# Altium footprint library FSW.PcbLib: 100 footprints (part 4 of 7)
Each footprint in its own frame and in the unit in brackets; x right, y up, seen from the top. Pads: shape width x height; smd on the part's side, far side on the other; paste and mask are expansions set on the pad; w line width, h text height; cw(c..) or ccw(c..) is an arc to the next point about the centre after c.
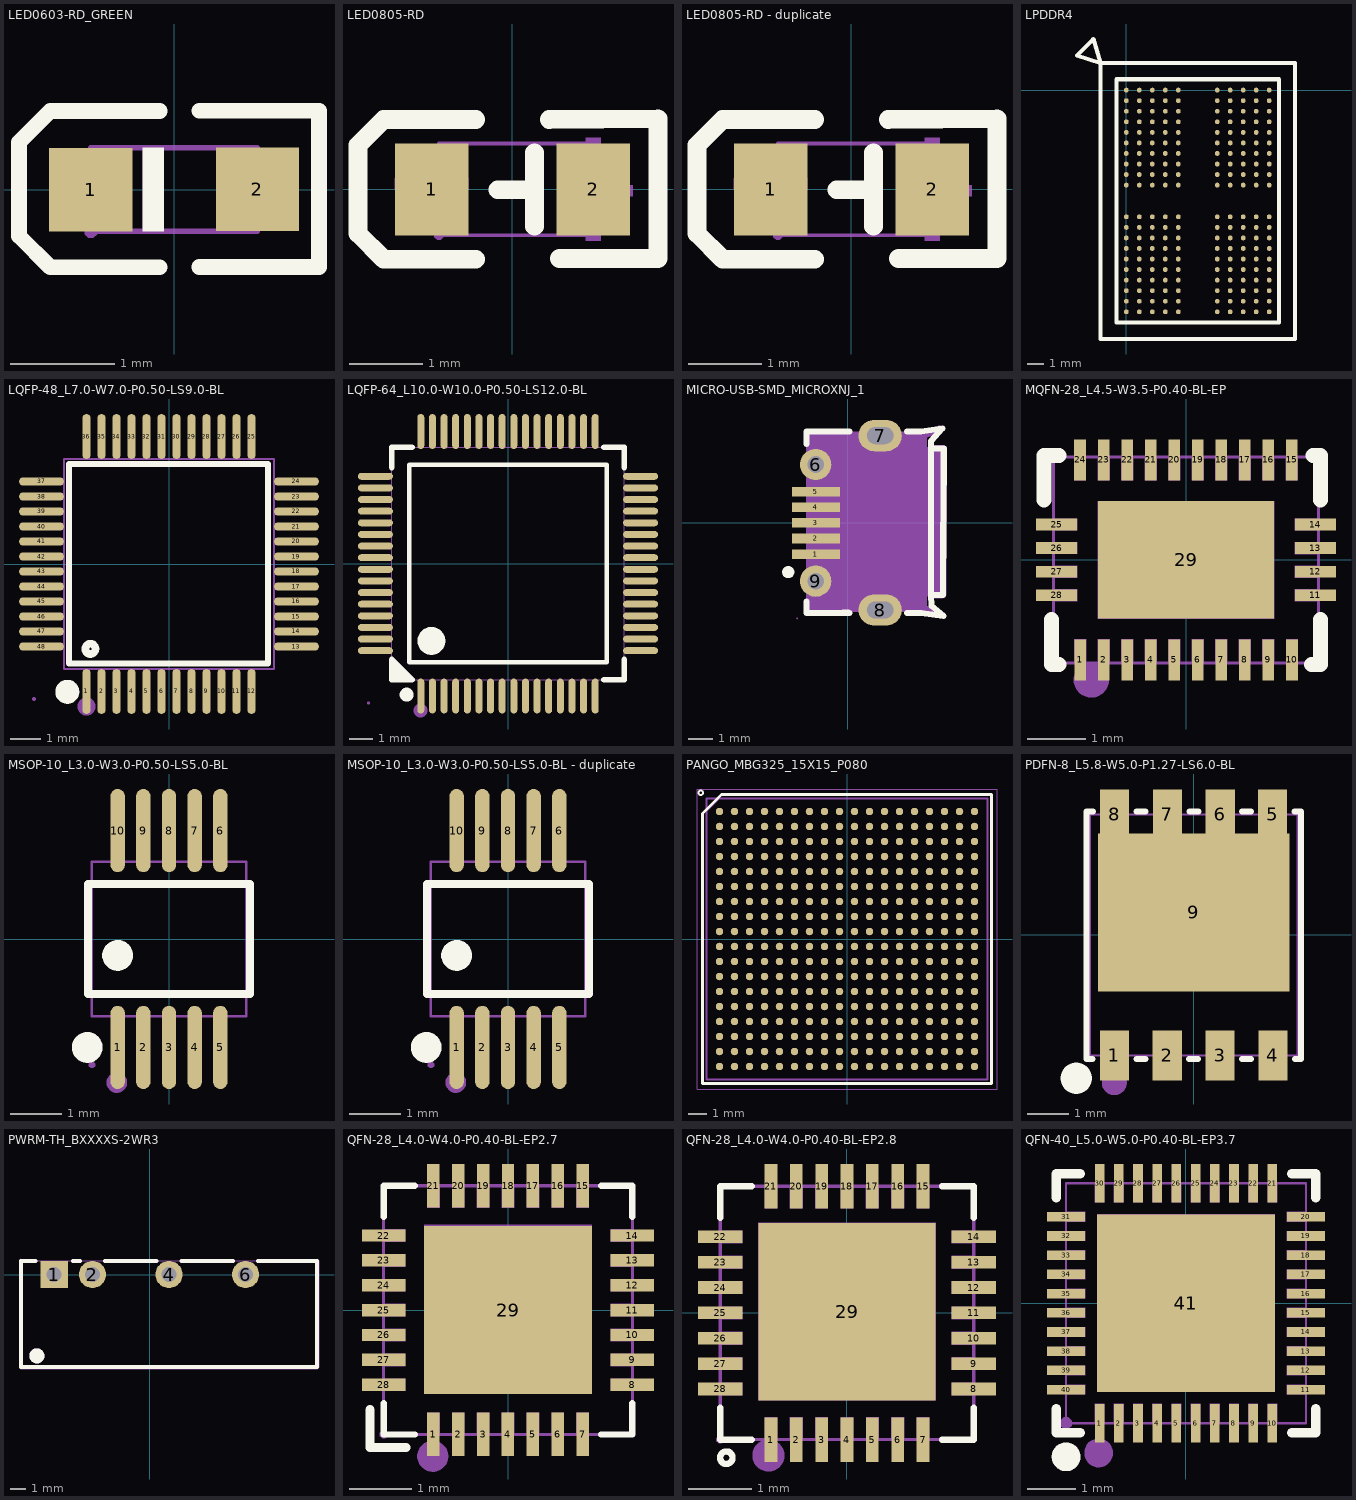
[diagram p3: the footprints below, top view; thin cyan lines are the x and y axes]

## LED0603-RD_GREEN [mm]
pads (2):
  rect 0.8x0.8 smd: 1(-0.799,-0.003) 2(0.799,0.003)
Top Overlay:
  region: -0.3,0.4 -0.3,-0.4 -0.1,-0.4 -0.1,0.4
  lines w0.15: -0.14,-0.746 -1.19,-0.746 -1.49,-0.446 -1.49,-0.346 -1.49,0.354 -1.49,0.454 -1.19,0.754 -0.14,0.754 ; 0.24,-0.744 1.39,-0.744 ; 0.24,0.757 1.39,0.757 1.39,-0.723
Mechanical 2:
  region: 0.529,0.068 1.069,0.068 1.069,-0.062 0.529,-0.062
  region: 0.735,-0.267 0.735,0.273 0.865,0.273 0.865,-0.267
  region: -1.07,0.062 -0.53,0.062 -0.53,-0.068 -1.07,-0.068
  region: -0.3,0.4 -0.3,-0.4 -0.1,-0.4 -0.1,0.4
Mechanical 6:
  lines w0.051: -0.8,-0.4 -0.8,0.4 0.8,0.4 0.8,-0.4 -0.8,-0.4
Mechanical 8:
  region: -0.74,-0.403 -0.74,-0.428 -0.775,-0.463 -0.824,-0.463 -0.86,-0.428 -0.86,-0.403 -0.86,-0.379 -0.824,-0.343 -0.775,-0.343 -0.74,-0.379 -0.74,-0.403
Mechanical 9:
  region: 0.5,-0.396 0.5,0.404 0.8,0.404 0.8,-0.396
  region: -0.8,-0.403 -0.8,0.397 -0.5,0.397 -0.5,-0.403
3D body "LED0603-RD-YELLOW.step": height 0.55, standoff -0.01, extent -0.81,-0.41 0.81,0.41

## LED0805-RD [mm]
pads (2):
  rect 1x1.25 smd: 1(-1.1,0) 2(1.1,0)
Top Overlay:
  lines w0.254: -0.5,-0.95 -1.75,-0.95 ; -0.5,0.95 -1.75,0.95 ; -0.2,-0.005 0.3,-0.005 ; 0.3,-0.5 0.3,0.5 ; 0.5,0.95 1.98,0.96 1.98,-0.94 0.64,-0.94 ; -1.75,-0.95 -2.1,-0.6 -2.1,0.6 -1.75,0.95 ; -1.75,-0.95 -1.75,-0.95 ; -1.75,0.95 -1.75,0.95
Mechanical 2:
  region: -1.6,0 -0.6,0 -0.6,0.15 -1.6,0.15
  region: 0.635,-0.094 1.635,-0.094 1.635,0.056 0.635,0.056
  region: 1,0.7 1.2,0.7 1.2,-0.7 1,-0.7
Mechanical 6:
  lines w0.051: -1,-0.625 1,-0.625 1,0.625 -1,0.625 -1,-0.625
Mechanical 8:
  region: -0.939,-0.625 -0.939,-0.65 -0.975,-0.686 -1.025,-0.686 -1.061,-0.65 -1.061,-0.625 -1.061,-0.6 -1.025,-0.564 -0.975,-0.564 -0.939,-0.6 -0.939,-0.625 -0.94,-0.625
Mechanical 9:
  region: -0.65,-0.625 -1,-0.625 -1,0.625 -0.65,0.625
  region: 1,-0.625 0.65,-0.625 0.65,0.625 1,0.625
3D body "LED0805-RD.step": height 1, standoff -0.01, extent -1.137,-0.625 0.883,0.635

## LED0805-RD - duplicate [mm]
pads (2):
  rect 1x1.25 smd: 1(-1.1,0) 2(1.1,0)
Top Overlay:
  lines w0.254: -0.5,-0.95 -1.75,-0.95 ; -0.5,0.95 -1.75,0.95 ; -0.2,-0.005 0.3,-0.005 ; 0.3,-0.5 0.3,0.5 ; 0.5,0.95 1.98,0.96 1.98,-0.94 0.64,-0.94 ; -1.75,-0.95 -2.1,-0.6 -2.1,0.6 -1.75,0.95 ; -1.75,-0.95 -1.75,-0.95 ; -1.75,0.95 -1.75,0.95
Mechanical 2:
  region: -1.6,0 -0.6,0 -0.6,0.15 -1.6,0.15
  region: 0.635,-0.094 1.635,-0.094 1.635,0.056 0.635,0.056
  region: 1,0.7 1.2,0.7 1.2,-0.7 1,-0.7
Mechanical 6:
  lines w0.051: -1,-0.625 1,-0.625 1,0.625 -1,0.625 -1,-0.625
Mechanical 8:
  region: -0.939,-0.625 -0.939,-0.65 -0.975,-0.686 -1.025,-0.686 -1.061,-0.65 -1.061,-0.625 -1.061,-0.6 -1.025,-0.564 -0.975,-0.564 -0.939,-0.6 -0.939,-0.625 -0.94,-0.625
Mechanical 9:
  region: -0.65,-0.625 -1,-0.625 -1,0.625 -0.65,0.625
  region: 1,-0.625 0.65,-0.625 0.65,0.625 1,0.625

## LPDDR4 [mm]
pads (200):
  round 0.3 smd paste+0.051: A1(0,0) A2(0.8,0) A3(1.6,0) A4(2.4,0) A5(3.2,0) A8(5.6,0) A9(6.4,0) A10(7.2,0) A11(8,0) A12(8.8,0) AA1(0,-13) AA2(0.8,-13) AA3(1.6,-13) AA4(2.4,-13) AA5(3.2,-13) AA8(5.6,-13) AA9(6.4,-13) AA10(7.2,-13) AA11(8,-13) AA12(8.8,-13) AB1(0,-13.65) AB2(0.8,-13.65) AB3(1.6,-13.65) AB4(2.4,-13.65) AB5(3.2,-13.65) AB8(5.6,-13.65) AB9(6.4,-13.65) AB10(7.2,-13.65) AB11(8,-13.65) AB12(8.8,-13.65) B1(0,-0.65) B2(0.8,-0.65) B3(1.6,-0.65) B4(2.4,-0.65) B5(3.2,-0.65) B8(5.6,-0.65) B9(6.4,-0.65) B10(7.2,-0.65) B11(8,-0.65) B12(8.8,-0.65) C1(0,-1.3) C2(0.8,-1.3) C3(1.6,-1.3) C4(2.4,-1.3) C5(3.2,-1.3) C8(5.6,-1.3) C9(6.4,-1.3) C10(7.2,-1.3) C11(8,-1.3) C12(8.8,-1.3) D1(0,-1.95) D2(0.8,-1.95) D3(1.6,-1.95) D4(2.4,-1.95) D5(3.2,-1.95) D8(5.6,-1.95) D9(6.4,-1.95) D10(7.2,-1.95) D11(8,-1.95) D12(8.8,-1.95) E1(0,-2.6) E2(0.8,-2.6) E3(1.6,-2.6) E4(2.4,-2.6) E5(3.2,-2.6) E8(5.6,-2.6) E9(6.4,-2.6) E10(7.2,-2.6) E11(8,-2.6) E12(8.8,-2.6) F1(0,-3.25) F2(0.8,-3.25) F3(1.6,-3.25) F4(2.4,-3.25) F5(3.2,-3.25) F8(5.6,-3.25) F9(6.4,-3.25) F10(7.2,-3.25) F11(8,-3.25) F12(8.8,-3.25) G1(0,-3.9) G2(0.8,-3.9) G3(1.6,-3.9) G4(2.4,-3.9) G5(3.2,-3.9) G8(5.6,-3.9) G9(6.4,-3.9) G10(7.2,-3.9) G11(8,-3.9) G12(8.8,-3.9) H1(0,-4.55) H2(0.8,-4.55) H3(1.6,-4.55) H4(2.4,-4.55) H5(3.2,-4.55) H8(5.6,-4.55) H9(6.4,-4.55) H10(7.2,-4.55) H11(8,-4.55) H12(8.8,-4.55) J1(0,-5.2) J2(0.8,-5.2) J3(1.6,-5.2) J4(2.4,-5.2) J5(3.2,-5.2) J8(5.6,-5.2) J9(6.4,-5.2) J10(7.2,-5.2) J11(8,-5.2) J12(8.8,-5.2) K1(0,-5.85) K2(0.8,-5.85) K3(1.6,-5.85) K4(2.4,-5.85) K5(3.2,-5.85) K8(5.6,-5.85) K9(6.4,-5.85) K10(7.2,-5.85) K11(8,-5.85) K12(8.8,-5.85) N1(0,-7.8) N2(0.8,-7.8) N3(1.6,-7.8) N4(2.4,-7.8) N5(3.2,-7.8) N8(5.6,-7.8) N9(6.4,-7.8) N10(7.2,-7.8) N11(8,-7.8) N12(8.8,-7.8) P1(0,-8.45) P2(0.8,-8.45) P3(1.6,-8.45) P4(2.4,-8.45) P5(3.2,-8.45) P8(5.6,-8.45) P9(6.4,-8.45) P10(7.2,-8.45) P11(8,-8.45) P12(8.8,-8.45) R1(0,-9.1) R2(0.8,-9.1) R3(1.6,-9.1) R4(2.4,-9.1) R5(3.2,-9.1) R8(5.6,-9.1) R9(6.4,-9.1) R10(7.2,-9.1) R11(8,-9.1) R12(8.8,-9.1) T1(0,-9.75) T2(0.8,-9.75) T3(1.6,-9.75) T4(2.4,-9.75) T5(3.2,-9.75) T8(5.6,-9.75) T9(6.4,-9.75) T10(7.2,-9.75) T11(8,-9.75) T12(8.8,-9.75) U1(0,-10.4) U2(0.8,-10.4) U3(1.6,-10.4) U4(2.4,-10.4) U5(3.2,-10.4) U8(5.6,-10.4) U9(6.4,-10.4) U10(7.2,-10.4) U11(8,-10.4) U12(8.8,-10.4) V1(0,-11.05) V2(0.8,-11.05) V3(1.6,-11.05) V4(2.4,-11.05) V5(3.2,-11.05) V8(5.6,-11.05) V9(6.4,-11.05) V10(7.2,-11.05) V11(8,-11.05) V12(8.8,-11.05) W1(0,-11.7) W2(0.8,-11.7) W3(1.6,-11.7) W4(2.4,-11.7) W5(3.2,-11.7) W8(5.6,-11.7) W9(6.4,-11.7) W10(7.2,-11.7) W11(8,-11.7) W12(8.8,-11.7) Y1(0,-12.35) Y2(0.8,-12.35) Y3(1.6,-12.35) Y4(2.4,-12.35) Y5(3.2,-12.35) Y8(5.6,-12.35) Y9(6.4,-12.35) Y10(7.2,-12.35) Y11(8,-12.35) Y12(8.8,-12.35)
Top Overlay:
  lines w0.254: -1.6,1.675 -1.6,-15.325 10.4,-15.325 10.4,1.675 -1.6,1.675 ; -1.6,1.675 -3.048,2.134 -2.032,3.15 -1.6,1.675 ; -0.6,-14.32 -0.6,0.67 9.4,0.67 9.4,-14.32 -0.6,-14.32
3D body "BGA-200_L15.0-W10.0_K4F8E304HB-MGCJ.step": height 0.9, standoff -0.01, extent -0.555,-14.358 9.445,0.642

## LQFP-48_L7.0-W7.0-P0.50-LS9.0-BL [mm]
pads (48):
  oval 0.27x1.5 smd paste+0 mask+0.05: 1(-2.75,-4.25) 2(-2.25,-4.25) 3(-1.75,-4.25) 4(-1.25,-4.25) 5(-0.75,-4.25) 6(-0.25,-4.25) 7(0.25,-4.25) 8(0.75,-4.25) 9(1.25,-4.25) 10(1.75,-4.25) 11(2.25,-4.25) 12(2.75,-4.25) 25(2.75,4.25) 26(2.25,4.25) 27(1.75,4.25) 28(1.25,4.25) 29(0.75,4.25) 30(0.25,4.25) 31(-0.25,4.25) 32(-0.75,4.25) 33(-1.25,4.25) 34(-1.75,4.25) 35(-2.25,4.25) 36(-2.75,4.25)
  oval 1.5x0.27 smd paste+0 mask+0.05: 13(4.25,-2.75) 14(4.25,-2.25) 15(4.25,-1.75) 16(4.25,-1.25) 17(4.25,-0.75) 18(4.25,-0.25) 19(4.25,0.25) 20(4.25,0.75) 21(4.25,1.25) 22(4.25,1.75) 23(4.25,2.25) 24(4.25,2.75) 37(-4.25,2.75) 38(-4.25,2.25) 39(-4.25,1.75) 40(-4.25,1.25) 41(-4.25,0.75) 42(-4.25,0.25) 43(-4.25,-0.25) 44(-4.25,-0.75) 45(-4.25,-1.25) 46(-4.25,-1.75) 47(-4.25,-2.25) 48(-4.25,-2.75)
Top Overlay:
  circle w0.254: c-2.62,-2.83 r0.17
  lines w0.2: -2.896,3.34 3.302,3.34 3.302,-3.315 -3.327,-3.315 -3.327,3.34 -2.565,3.34
  lines w0.4: -3.39,-4.06 ccw(c-3.389,-4.26) -3.387,-4.06
Mechanical 2:
  circle w0.3: c-2.75,-4.75 r0.15
Mechanical 6:
  lines w0.051: -3.5,-3.5 3.5,-3.5 3.5,3.5 -3.5,3.5 -3.5,-3.5
Mechanical 7:
  drawing of 48 lines, arcs and shapes, not listed
Mechanical 8:
  region: -4.44,-4.5 -4.44,-4.525 -4.475,-4.56 -4.525,-4.56 -4.56,-4.525 -4.56,-4.5 -4.56,-4.475 -4.525,-4.44 -4.475,-4.44 -4.44,-4.475 -4.44,-4.5
Mechanical 9:
  drawing of 48 lines, arcs and shapes, not listed

## LQFP-64_L10.0-W10.0-P0.50-LS12.0-BL [mm]
pads (64):
  oval 0.3x1.5 smd: 1(-3.75,-5.688) 2(-3.25,-5.688) 3(-2.75,-5.688) 4(-2.25,-5.688) 5(-1.75,-5.688) 6(-1.25,-5.688) 7(-0.75,-5.688) 8(-0.25,-5.688) 9(0.25,-5.688) 10(0.75,-5.688) 11(1.25,-5.688) 12(1.75,-5.688) 13(2.25,-5.688) 14(2.75,-5.688) 15(3.25,-5.688) 16(3.75,-5.688) 33(3.75,5.688) 34(3.25,5.688) 35(2.75,5.688) 36(2.25,5.688) 37(1.75,5.688) 38(1.25,5.688) 39(0.75,5.688) 40(0.25,5.688) 41(-0.25,5.688) 42(-0.75,5.688) 43(-1.25,5.688) 44(-1.75,5.688) 45(-2.25,5.688) 46(-2.75,5.688) 47(-3.25,5.688) 48(-3.75,5.688)
  oval 1.5x0.3 smd: 17(5.7,-3.738) 18(5.7,-3.238) 19(5.7,-2.738) 20(5.7,-2.238) 21(5.7,-1.738) 22(5.7,-1.238) 23(5.7,-0.738) 24(5.7,-0.238) 25(5.7,0.262) 26(5.7,0.762) 27(5.7,1.262) 28(5.7,1.762) 29(5.7,2.262) 30(5.7,2.762) 31(5.7,3.262) 32(5.7,3.762) 49(-5.7,3.762) 50(-5.7,3.262) 51(-5.7,2.762) 52(-5.7,2.262) 53(-5.7,1.762) 54(-5.7,1.262) 55(-5.7,0.762) 56(-5.7,0.262) 57(-5.7,-0.238) 58(-5.7,-0.738) 59(-5.7,-1.238) 60(-5.7,-1.738) 61(-5.7,-2.238) 62(-5.7,-2.738) 63(-5.7,-3.238) 64(-5.7,-3.738)
Top Overlay:
  region: -4.131,-4.988 -5,-4.119 -5,-4.988
  lines w0.2: -4.25,-4.238 -4.25,4.262 4.25,4.262 4.25,-4.238 -4.25,-4.238
  lines w0.254: -5,4.143 -5,5.012 -4.131,5.012 ; 4.131,-4.988 5,-4.988 5,-4.119 ; 4.131,5.012 5,5.012 5,4.143 ; -5,-4.119 -5,-4.119 ; -5,-4.119 -4.131,-4.988 -5,-4.988 -5,-4.119
  lines w0.3: -4.361,-5.478 ccw(c-4.36,-5.628) -4.359,-5.478
  lines w0.6: -3.299,-3.013 ccw(c-3.297,-3.313) -3.294,-3.013
Mechanical 2:
  circle w0.3: c-3.76,-6.308 r0.15
Mechanical 6:
  lines w0.051: -5,-4.988 5,-4.988 5,5.012 -5,5.012 -5,-4.988
Mechanical 7:
  drawing of 64 lines, arcs and shapes, not listed
Mechanical 8:
  region: -5.94,-5.988 -5.94,-6.013 -5.975,-6.048 -6.025,-6.048 -6.06,-6.013 -6.06,-5.988 -6.06,-5.963 -6.025,-5.928 -5.975,-5.928 -5.94,-5.963 -5.94,-5.988
Mechanical 9:
  drawing of 64 lines, arcs and shapes, not listed

## MICRO-USB-SMD_MICROXNJ_1 [mm]
pads (9):
  rect 2x0.4 smd paste-100 mask+0.051: 1(-1.332,-1.3) 2(-1.332,-0.65) 3(-1.332,0) 4(-1.332,0.65) 5(-1.332,1.3)
  round 1.3 hole 0.7 paste-2539.97 mask+0.051: 6(-1.34,2.425) 9(-1.34,-2.425)
  oval 1.8x1.3 hole 0.7 slot 1.1 at 0 deg paste-2539.97 mask+0.051: 7(1.34,3.625) 8(1.34,-3.625)
Mid-Layer 2:
  lines w0.1: -4.186,-7.897 ccw(c-4.136,-7.897) -4.086,-7.897 ccw(c-4.136,-7.897) -4.186,-7.897
Top Overlay:
  lines w0.254: -1.725,-3.274 -1.725,-3.745 0.058,-3.745 ; -1.725,3.274 -1.725,3.79 0.066,3.79 ; -0.196,-3.731 0.012,-3.735 ; -0.163,-3.732 0.012,-3.733 ; 2.448,3.79 3.041,3.79 ; 2.456,-3.745 3.052,-3.745 3.967,-3.87 3.471,-3.45 3.451,-3 ; 3.041,3.8 3.926,3.93 3.451,3.4 3.451,3.1 ; 3.451,-3 3.451,3.1 ; 3.451,-3 3.951,-3 3.981,3.09 3.451,3.1 ; -2.61,-2.049 ccw(c-2.483,-2.049) -2.356,-2.049 ccw(c-2.483,-2.049) -2.61,-2.049
Top Paste:
  region: -1.957,-1.125 -1.957,-1.475 -0.707,-1.475 -0.707,-1.125
  region: -1.957,-0.475 -1.957,-0.825 -0.707,-0.825 -0.707,-0.475
  region: -1.957,1.475 -1.957,1.125 -0.707,1.125 -0.707,1.475
  region: -1.957,0.825 -1.957,0.475 -0.707,0.475 -0.707,0.825
  region: -1.957,0.175 -1.957,-0.175 -0.707,-0.175 -0.707,0.175
Mechanical 5:
  region: 3.451,-2.873 3.825,-2.873 3.854,2.965 3.449,2.973 3.401,2.984 3.361,3.012 3.334,3.054 3.325,3.102 3.336,3.151 3.364,3.191 3.405,3.218 3.454,3.227 3.984,3.217 4.032,3.207 4.072,3.179 4.099,3.138 4.108,3.089 4.078,-3.001 4.069,-3.049 4.041,-3.09 4,-3.117 3.951,-3.127 3.451,-3.127 3.403,-3.117 3.362,-3.09 3.334,-3.049 3.324,-3 3.334,-2.951 3.362,-2.91 3.403,-2.883
Mechanical 9:
  region: -1.725,-3.7 -1.725,3.79 3.255,3.79 3.805,4.05 3.865,4.03 3.865,3.83 3.275,3.54 3.275,3.15 3.875,3.15 3.865,-3.03 3.865,-3.05 3.275,-3.05 3.275,-3.45 3.875,-3.74 3.865,-3.97 3.265,-3.7 -1.715,-3.7
Mechanical 11:
  region: -2.08,-3.97 -2.089,-3.949 -2.11,-3.94 -2.131,-3.949 -2.14,-3.97 -2.131,-3.991 -2.11,-4 -2.089,-3.991
Mechanical 12:
  region: -1.11,1.175 -2.11,1.175 -2.11,1.425 -1.11,1.425
  region: -1.11,0.525 -2.11,0.525 -2.11,0.775 -1.11,0.775
  region: -1.11,-0.125 -2.11,-0.125 -2.11,0.125 -1.11,0.125
  region: -1.11,-0.775 -2.11,-0.775 -2.11,-0.525 -1.11,-0.525
  region: -1.11,-1.425 -2.11,-1.425 -2.11,-1.175 -1.11,-1.175
  region: 0.875,-3.775 0.875,-3.475 1.785,-3.475 1.785,-3.775
  region: 0.875,3.475 0.875,3.775 1.785,3.775 1.785,3.475
  region: -1.24,-2.675 -1.44,-2.675 -1.44,-2.175 -1.24,-2.175
  region: -1.24,2.175 -1.44,2.175 -1.44,2.675 -1.24,2.675
3D body "MICRO-USB-SMD_MICROXNJ_1.step": height 2.71, standoff -0.95, extent -1.9,-4 4.064,4

## MQFN-28_L4.5-W3.5-P0.40-BL-EP [mm]
pads (29):
  rect 0.2x0.7 smd paste-100 mask+0.051: 1(-1.8,-1.7) 2(-1.4,-1.7) 3(-1,-1.7) 4(-0.6,-1.7) 5(-0.2,-1.7) 6(0.2,-1.7) 7(0.6,-1.7) 8(1,-1.7) 9(1.4,-1.7) 10(1.8,-1.7) 15(1.8,1.7) 16(1.4,1.7) 17(1,1.7) 18(0.6,1.7) 19(0.2,1.7) 20(-0.2,1.7) 21(-0.6,1.7) 22(-1,1.7) 23(-1.4,1.7) 24(-1.8,1.7)
  rect 0.7x0.2 smd paste-100 mask+0.051: 11(2.2,-0.6) 12(2.2,-0.2) 13(2.2,0.2) 14(2.2,0.6) 25(-2.2,0.6) 26(-2.2,0.2) 27(-2.2,-0.2) 28(-2.2,-0.6)
  rect 3x2 smd paste-100 mask+0.051: 29(0,0)
Top Overlay:
  lines w0.254: -2.413,1.016 -2.413,1.778 -2.159,1.778 ; -2.286,-1.016 -2.286,-1.778 -2.159,-1.778 ; 2.131,-1.778 2.286,-1.778 2.286,-1.016 ; 2.159,1.778 2.286,1.778 2.286,1.016
Top Paste:
  region: -1.2,0.8 1.2,0.8 1.2,-0.8 -1.2,-0.8
  region: -0.1,-2.05 -0.1,-1.35 -0.3,-1.35 -0.3,-2.05
  region: 0.1,-1.35 0.1,-2.05 0.3,-2.05 0.3,-1.35
  region: -0.5,-2.05 -0.5,-1.35 -0.7,-1.35 -0.7,-2.05
  region: -0.9,-2.05 -0.9,-1.35 -1.1,-1.35 -1.1,-2.05
  region: -1.3,-2.05 -1.3,-1.35 -1.5,-1.35 -1.5,-2.05
  region: 0.5,-1.35 0.5,-2.05 0.7,-2.05 0.7,-1.35
  region: -1.7,-2.05 -1.7,-1.35 -1.9,-1.35 -1.9,-2.05
  region: 0.9,-1.35 0.9,-2.05 1.1,-2.05 1.1,-1.35
  region: 1.3,-1.35 1.3,-2.05 1.5,-2.05 1.5,-1.35
  region: 1.7,-1.35 1.7,-2.05 1.9,-2.05 1.9,-1.35
  region: -1.85,-0.7 -1.85,-0.5 -2.55,-0.5 -2.55,-0.7
  region: 2.55,-0.7 2.55,-0.5 1.85,-0.5 1.85,-0.7
  region: -1.85,-0.3 -1.85,-0.1 -2.55,-0.1 -2.55,-0.3
  region: 1.85,-0.1 1.85,-0.3 2.55,-0.3 2.55,-0.1
  region: -1.85,0.1 -1.85,0.3 -2.55,0.3 -2.55,0.1
  region: 1.85,0.3 1.85,0.1 2.55,0.1 2.55,0.3
  region: -1.85,0.5 -1.85,0.7 -2.55,0.7 -2.55,0.5
  region: 1.85,0.7 1.85,0.5 2.55,0.5 2.55,0.7
  region: -1.9,2.05 -1.9,1.35 -1.7,1.35 -1.7,2.05
  region: 0.3,1.35 0.3,2.05 0.1,2.05 0.1,1.35
  region: -0.3,2.05 -0.3,1.35 -0.1,1.35 -0.1,2.05
  region: 0.7,1.35 0.7,2.05 0.5,2.05 0.5,1.35
  region: 1.1,1.35 1.1,2.05 0.9,2.05 0.9,1.35
  region: 1.5,1.35 1.5,2.05 1.3,2.05 1.3,1.35
  region: -1.5,2.05 -1.5,1.35 -1.3,1.35 -1.3,2.05
  region: -0.7,2.05 -0.7,1.35 -0.5,1.35 -0.5,2.05
  region: -0.9,1.35 -0.9,2.05 -1.1,2.05 -1.1,1.35
  region: 1.9,1.35 1.9,2.05 1.7,2.05 1.7,1.35
Mechanical 2:
  circle w0.3: c-1.61,-2.04 r0.15
Mechanical 6:
  lines w0.051: -2.25,-1.75 -2.25,1.75 2.25,1.75 2.25,-1.75 -2.25,-1.75
Mechanical 8:
  region: -2.19,-1.75 -2.19,-1.775 -2.225,-1.81 -2.275,-1.81 -2.31,-1.775 -2.31,-1.75 -2.31,-1.725 -2.275,-1.69 -2.225,-1.69 -2.19,-1.725 -2.19,-1.75
Mechanical 9:
  region: -1.5,1 1.5,1 1.5,-1 -1.5,-1
  region: 1.85,-0.7 1.85,-0.5 2.25,-0.5 2.25,-0.7
  region: 1.85,-0.3 1.85,-0.1 2.25,-0.1 2.25,-0.3
  region: 1.85,0.1 1.85,0.3 2.25,0.3 2.25,0.1
  region: 1.85,0.5 1.85,0.7 2.25,0.7 2.25,0.5
  region: -1.85,0.7 -1.85,0.5 -2.25,0.5 -2.25,0.7
  region: -1.85,0.3 -1.85,0.1 -2.25,0.1 -2.25,0.3
  region: -1.85,-0.1 -1.85,-0.3 -2.25,-0.3 -2.25,-0.1
  region: -1.85,-0.5 -1.85,-0.7 -2.25,-0.7 -2.25,-0.5
  region: 1.9,1.35 1.7,1.35 1.7,1.75 1.9,1.75
  region: 1.5,1.35 1.3,1.35 1.3,1.75 1.5,1.75
  region: 1.1,1.35 0.9,1.35 0.9,1.75 1.1,1.75
  region: 0.7,1.35 0.5,1.35 0.5,1.75 0.7,1.75
  region: 0.3,1.35 0.1,1.35 0.1,1.75 0.3,1.75
  region: -0.1,1.35 -0.3,1.35 -0.3,1.75 -0.1,1.75
  region: -0.5,1.35 -0.7,1.35 -0.7,1.75 -0.5,1.75
  region: -0.9,1.35 -1.1,1.35 -1.1,1.75 -0.9,1.75
  region: -1.3,1.35 -1.5,1.35 -1.5,1.75 -1.3,1.75
  region: -1.7,1.35 -1.9,1.35 -1.9,1.75 -1.7,1.75
  region: 1.7,-1.35 1.9,-1.35 1.9,-1.75 1.7,-1.75
  region: 1.3,-1.35 1.5,-1.35 1.5,-1.75 1.3,-1.75
  region: 0.9,-1.35 1.1,-1.35 1.1,-1.75 0.9,-1.75
  region: 0.5,-1.35 0.7,-1.35 0.7,-1.75 0.5,-1.75
  region: 0.1,-1.35 0.3,-1.35 0.3,-1.75 0.1,-1.75
  region: -0.3,-1.35 -0.1,-1.35 -0.1,-1.75 -0.3,-1.75
  region: -0.7,-1.35 -0.5,-1.35 -0.5,-1.75 -0.7,-1.75
  region: -1.1,-1.35 -0.9,-1.35 -0.9,-1.75 -1.1,-1.75
  region: -1.5,-1.35 -1.3,-1.35 -1.3,-1.75 -1.5,-1.75
  region: -1.9,-1.35 -1.7,-1.35 -1.7,-1.75 -1.9,-1.75
3D body "MQFN-28_L4.5-W3.5-P0.40-BL-EP.step": height 0.84, standoff -0.02, extent -2.26,-1.76 2.26,1.76

## MSOP-10_L3.0-W3.0-P0.50-LS5.0-BL [mm]
pads (10):
  oval 0.28x1.62 smd: 1(-1,-2.11) 2(-0.5,-2.11) 3(0,-2.11) 4(0.5,-2.11) 5(1,-2.11) 6(1,2.11) 7(0.5,2.11) 8(0,2.11) 9(-0.5,2.11) 10(-1,2.11)
Top Overlay:
  circle w0.3: c-1,-0.319 r0.15
  circle w0.3: c-1.592,-2.11 r0.15
  lines w0.152: -1.576,-1.071 -1.576,1.071 1.576,1.071 1.576,-1.071 -1.576,-1.071
Mechanical 2:
  circle w0.2: c-1.016,-2.794 r0.1
Mechanical 6:
  lines w0.051: -1.5,-1.5 -1.5,1.5 1.5,1.5 1.5,-1.5 -1.5,-1.5
Mechanical 7:
  region: -1.112,-1.91 -1.112,-1.49 -0.888,-1.49 -0.888,-1.91
  region: -0.612,-1.91 -0.612,-1.49 -0.388,-1.49 -0.388,-1.91
  region: -0.112,-1.91 -0.112,-1.49 0.112,-1.49 0.112,-1.91
  region: 0.388,-1.91 0.388,-1.49 0.612,-1.49 0.612,-1.91
  region: 0.888,-1.91 0.888,-1.49 1.112,-1.49 1.112,-1.91
  region: -1.112,1.91 -1.112,1.49 -0.888,1.49 -0.888,1.91
  region: -0.612,1.91 -0.612,1.49 -0.388,1.49 -0.388,1.91
  region: -0.112,1.91 -0.112,1.49 0.112,1.49 0.112,1.91
  region: 0.388,1.91 0.388,1.49 0.612,1.49 0.612,1.91
  region: 0.888,1.91 0.888,1.49 1.112,1.49 1.112,1.91
Mechanical 8:
  region: -1.44,-2.45 -1.44,-2.475 -1.475,-2.51 -1.525,-2.51 -1.56,-2.475 -1.56,-2.45 -1.56,-2.425 -1.525,-2.39 -1.475,-2.39 -1.44,-2.425 -1.44,-2.45
Mechanical 9:
  region: -1.112,-2.45 -1.112,-1.9 -0.888,-1.9 -0.888,-2.45
  region: -0.612,-2.45 -0.612,-1.9 -0.388,-1.9 -0.388,-2.45
  region: -0.112,-2.45 -0.112,-1.9 0.112,-1.9 0.112,-2.45
  region: 0.388,-2.45 0.388,-1.9 0.612,-1.9 0.612,-2.45
  region: 0.888,-2.45 0.888,-1.9 1.112,-1.9 1.112,-2.45
  region: -1.112,2.45 -1.112,1.9 -0.888,1.9 -0.888,2.45
  region: -0.612,2.45 -0.612,1.9 -0.388,1.9 -0.388,2.45
  region: -0.112,2.45 -0.112,1.9 0.112,1.9 0.112,2.45
  region: 0.388,2.45 0.388,1.9 0.612,1.9 0.612,2.45
  region: 0.888,2.45 0.888,1.9 1.112,1.9 1.112,2.45

## MSOP-10_L3.0-W3.0-P0.50-LS5.0-BL - duplicate [mm]
pads (10):
  oval 0.28x1.62 smd: 1(-1,-2.11) 2(-0.5,-2.11) 3(0,-2.11) 4(0.5,-2.11) 5(1,-2.11) 6(1,2.11) 7(0.5,2.11) 8(0,2.11) 9(-0.5,2.11) 10(-1,2.11)
Top Overlay:
  circle w0.3: c-1,-0.319 r0.15
  circle w0.3: c-1.592,-2.11 r0.15
  lines w0.152: -1.576,-1.071 -1.576,1.071 1.576,1.071 1.576,-1.071 -1.576,-1.071
Mechanical 2:
  circle w0.2: c-1.016,-2.794 r0.1
Mechanical 6:
  lines w0.051: -1.5,-1.5 -1.5,1.5 1.5,1.5 1.5,-1.5 -1.5,-1.5
Mechanical 7:
  region: -1.112,-1.91 -1.112,-1.49 -0.888,-1.49 -0.888,-1.91
  region: -0.612,-1.91 -0.612,-1.49 -0.388,-1.49 -0.388,-1.91
  region: -0.112,-1.91 -0.112,-1.49 0.112,-1.49 0.112,-1.91
  region: 0.388,-1.91 0.388,-1.49 0.612,-1.49 0.612,-1.91
  region: 0.888,-1.91 0.888,-1.49 1.112,-1.49 1.112,-1.91
  region: -1.112,1.91 -1.112,1.49 -0.888,1.49 -0.888,1.91
  region: -0.612,1.91 -0.612,1.49 -0.388,1.49 -0.388,1.91
  region: -0.112,1.91 -0.112,1.49 0.112,1.49 0.112,1.91
  region: 0.388,1.91 0.388,1.49 0.612,1.49 0.612,1.91
  region: 0.888,1.91 0.888,1.49 1.112,1.49 1.112,1.91
Mechanical 8:
  region: -1.44,-2.45 -1.44,-2.475 -1.475,-2.51 -1.525,-2.51 -1.56,-2.475 -1.56,-2.45 -1.56,-2.425 -1.525,-2.39 -1.475,-2.39 -1.44,-2.425 -1.44,-2.45
Mechanical 9:
  region: -1.112,-2.45 -1.112,-1.9 -0.888,-1.9 -0.888,-2.45
  region: -0.612,-2.45 -0.612,-1.9 -0.388,-1.9 -0.388,-2.45
  region: -0.112,-2.45 -0.112,-1.9 0.112,-1.9 0.112,-2.45
  region: 0.388,-2.45 0.388,-1.9 0.612,-1.9 0.612,-2.45
  region: 0.888,-2.45 0.888,-1.9 1.112,-1.9 1.112,-2.45
  region: -1.112,2.45 -1.112,1.9 -0.888,1.9 -0.888,2.45
  region: -0.612,2.45 -0.612,1.9 -0.388,1.9 -0.388,2.45
  region: -0.112,2.45 -0.112,1.9 0.112,1.9 0.112,2.45
  region: 0.388,2.45 0.388,1.9 0.612,1.9 0.612,2.45
  region: 0.888,2.45 0.888,1.9 1.112,1.9 1.112,2.45

## PANGO_MBG325_15X15_P080 [mm] "PK04004 V1.1: 324 balls, 15x15mm, 0.8mm pitch; top-view A1 upper-left; nominal 3D 1.30mm, max height 1.45mm"
height 1.45
pads (324):
  round 0.4 smd paste+0 mask+0.05: A1(-6.8,6.8) A2(-6,6.8) A3(-5.2,6.8) A4(-4.4,6.8) A5(-3.6,6.8) A6(-2.8,6.8) A7(-2,6.8) A8(-1.2,6.8) A9(-0.4,6.8) A10(0.4,6.8) A11(1.2,6.8) A12(2,6.8) A13(2.8,6.8) A14(3.6,6.8) A15(4.4,6.8) A16(5.2,6.8) A17(6,6.8) A18(6.8,6.8) B1(-6.8,6) B2(-6,6) B3(-5.2,6) B4(-4.4,6) B5(-3.6,6) B6(-2.8,6) B7(-2,6) B8(-1.2,6) B9(-0.4,6) B10(0.4,6) B11(1.2,6) B12(2,6) B13(2.8,6) B14(3.6,6) B15(4.4,6) B16(5.2,6) B17(6,6) B18(6.8,6) C1(-6.8,5.2) C2(-6,5.2) C3(-5.2,5.2) C4(-4.4,5.2) C5(-3.6,5.2) C6(-2.8,5.2) C7(-2,5.2) C8(-1.2,5.2) C9(-0.4,5.2) C10(0.4,5.2) C11(1.2,5.2) C12(2,5.2) C13(2.8,5.2) C14(3.6,5.2) C15(4.4,5.2) C16(5.2,5.2) C17(6,5.2) C18(6.8,5.2) D1(-6.8,4.4) D2(-6,4.4) D3(-5.2,4.4) D4(-4.4,4.4) D5(-3.6,4.4) D6(-2.8,4.4) D7(-2,4.4) D8(-1.2,4.4) D9(-0.4,4.4) D10(0.4,4.4) D11(1.2,4.4) D12(2,4.4) D13(2.8,4.4) D14(3.6,4.4) D15(4.4,4.4) D16(5.2,4.4) D17(6,4.4) D18(6.8,4.4) E1(-6.8,3.6) E2(-6,3.6) E3(-5.2,3.6) E4(-4.4,3.6) E5(-3.6,3.6) E6(-2.8,3.6) E7(-2,3.6) E8(-1.2,3.6) E9(-0.4,3.6) E10(0.4,3.6) E11(1.2,3.6) E12(2,3.6) E13(2.8,3.6) E14(3.6,3.6) E15(4.4,3.6) E16(5.2,3.6) E17(6,3.6) E18(6.8,3.6) F1(-6.8,2.8) F2(-6,2.8) F3(-5.2,2.8) F4(-4.4,2.8) F5(-3.6,2.8) F6(-2.8,2.8) F7(-2,2.8) F8(-1.2,2.8) F9(-0.4,2.8) F10(0.4,2.8) F11(1.2,2.8) F12(2,2.8) F13(2.8,2.8) F14(3.6,2.8) F15(4.4,2.8) F16(5.2,2.8) F17(6,2.8) F18(6.8,2.8) G1(-6.8,2) G2(-6,2) G3(-5.2,2) G4(-4.4,2) G5(-3.6,2) G6(-2.8,2) G7(-2,2) G8(-1.2,2) G9(-0.4,2) G10(0.4,2) G11(1.2,2) G12(2,2) G13(2.8,2) G14(3.6,2) G15(4.4,2) G16(5.2,2) G17(6,2) G18(6.8,2) H1(-6.8,1.2) H2(-6,1.2) H3(-5.2,1.2) H4(-4.4,1.2) H5(-3.6,1.2) H6(-2.8,1.2) H7(-2,1.2) H8(-1.2,1.2) H9(-0.4,1.2) H10(0.4,1.2) H11(1.2,1.2) H12(2,1.2) H13(2.8,1.2) H14(3.6,1.2) H15(4.4,1.2) H16(5.2,1.2) H17(6,1.2) H18(6.8,1.2) J1(-6.8,0.4) J2(-6,0.4) J3(-5.2,0.4) J4(-4.4,0.4) J5(-3.6,0.4) J6(-2.8,0.4) J7(-2,0.4) J8(-1.2,0.4) J9(-0.4,0.4) J10(0.4,0.4) J11(1.2,0.4) J12(2,0.4) J13(2.8,0.4) J14(3.6,0.4) J15(4.4,0.4) J16(5.2,0.4) J17(6,0.4) J18(6.8,0.4) K1(-6.8,-0.4) K2(-6,-0.4) K3(-5.2,-0.4) K4(-4.4,-0.4) K5(-3.6,-0.4) K6(-2.8,-0.4) K7(-2,-0.4) K8(-1.2,-0.4) K9(-0.4,-0.4) K10(0.4,-0.4) K11(1.2,-0.4) K12(2,-0.4) K13(2.8,-0.4) K14(3.6,-0.4) K15(4.4,-0.4) K16(5.2,-0.4) K17(6,-0.4) K18(6.8,-0.4) L1(-6.8,-1.2) L2(-6,-1.2) L3(-5.2,-1.2) L4(-4.4,-1.2) L5(-3.6,-1.2) L6(-2.8,-1.2) L7(-2,-1.2) L8(-1.2,-1.2) L9(-0.4,-1.2) L10(0.4,-1.2) L11(1.2,-1.2) L12(2,-1.2) L13(2.8,-1.2) L14(3.6,-1.2) L15(4.4,-1.2) L16(5.2,-1.2) L17(6,-1.2) L18(6.8,-1.2) M1(-6.8,-2) M2(-6,-2) M3(-5.2,-2) M4(-4.4,-2) M5(-3.6,-2) M6(-2.8,-2) M7(-2,-2) M8(-1.2,-2) M9(-0.4,-2) M10(0.4,-2) M11(1.2,-2) M12(2,-2) M13(2.8,-2) M14(3.6,-2) M15(4.4,-2) M16(5.2,-2) M17(6,-2) M18(6.8,-2) N1(-6.8,-2.8) N2(-6,-2.8) N3(-5.2,-2.8) N4(-4.4,-2.8) N5(-3.6,-2.8) N6(-2.8,-2.8) N7(-2,-2.8) N8(-1.2,-2.8) N9(-0.4,-2.8) N10(0.4,-2.8) N11(1.2,-2.8) N12(2,-2.8) N13(2.8,-2.8) N14(3.6,-2.8) N15(4.4,-2.8) N16(5.2,-2.8) N17(6,-2.8) N18(6.8,-2.8) P1(-6.8,-3.6) P2(-6,-3.6) P3(-5.2,-3.6) P4(-4.4,-3.6) P5(-3.6,-3.6) P6(-2.8,-3.6) P7(-2,-3.6) P8(-1.2,-3.6) P9(-0.4,-3.6) P10(0.4,-3.6) P11(1.2,-3.6) P12(2,-3.6) P13(2.8,-3.6) P14(3.6,-3.6) P15(4.4,-3.6) P16(5.2,-3.6) P17(6,-3.6) P18(6.8,-3.6) R1(-6.8,-4.4) R2(-6,-4.4) R3(-5.2,-4.4) R4(-4.4,-4.4) R5(-3.6,-4.4) R6(-2.8,-4.4) R7(-2,-4.4) R8(-1.2,-4.4) R9(-0.4,-4.4) R10(0.4,-4.4) R11(1.2,-4.4) R12(2,-4.4) R13(2.8,-4.4) R14(3.6,-4.4) R15(4.4,-4.4) R16(5.2,-4.4) R17(6,-4.4) R18(6.8,-4.4) T1(-6.8,-5.2) T2(-6,-5.2) T3(-5.2,-5.2) T4(-4.4,-5.2) T5(-3.6,-5.2) T6(-2.8,-5.2) T7(-2,-5.2) T8(-1.2,-5.2) T9(-0.4,-5.2) T10(0.4,-5.2) T11(1.2,-5.2) T12(2,-5.2) T13(2.8,-5.2) T14(3.6,-5.2) T15(4.4,-5.2) T16(5.2,-5.2) T17(6,-5.2) T18(6.8,-5.2) U1(-6.8,-6) U2(-6,-6) U3(-5.2,-6) U4(-4.4,-6) U5(-3.6,-6) U6(-2.8,-6) U7(-2,-6) U8(-1.2,-6) U9(-0.4,-6) U10(0.4,-6) U11(1.2,-6) U12(2,-6) U13(2.8,-6) U14(3.6,-6) U15(4.4,-6) U16(5.2,-6) U17(6,-6) U18(6.8,-6) V1(-6.8,-6.8) V2(-6,-6.8) V3(-5.2,-6.8) V4(-4.4,-6.8) V5(-3.6,-6.8) V6(-2.8,-6.8) V7(-2,-6.8) V8(-1.2,-6.8) V9(-0.4,-6.8) V10(0.4,-6.8) V11(1.2,-6.8) V12(2,-6.8) V13(2.8,-6.8) V14(3.6,-6.8) V15(4.4,-6.8) V16(5.2,-6.8) V17(6,-6.8) V18(6.8,-6.8)
Top Overlay:
  circle w0.1: c-7.8,7.8 r0.12
  lines w0.15: -7.7,-7.7 -7.7,6.7 -6.7,7.7 7.7,7.7 7.7,-7.7 -7.7,-7.7
Mechanical 1:
  lines w0.1: -7.5,6.8 -6.8,7.5 ; -7.5,-7.5 -7.5,7.5 7.5,7.5 7.5,-7.5 -7.5,-7.5
Mechanical 15:
  lines w0.05: -8,-8 -8,8 8,8 8,-8 -8,-8
3D body: height 1.3, standoff 0.34, extent -7.5,-7.5 7.5,7.5

## PDFN-8_L5.8-W5.0-P1.27-LS6.0-BL [mm]
pads (9):
  rect 0.701x1.199 smd paste-100 mask+0.051: 1(-1.905,-2.901) 2(-0.635,-2.901) 3(0.635,-2.901) 4(1.905,-2.901) 5(1.9,2.898) 6(0.64,2.898) 7(-0.63,2.898) 8(-1.9,2.898)
  rect 4.6x3.8 smd paste-100 mask+0.051: 9(0,0.538)
Top Overlay:
  lines w0.15: -2.578,2.969 -2.578,-2.99 -2.433,-2.99 ; -2.568,2.969 -2.428,2.969 ; -1.374,-2.99 -1.163,-2.99 ; -1.369,2.969 -1.158,2.969 ; -0.104,-2.99 0.107,-2.99 ; -0.099,2.969 0.112,2.969 ; 1.166,-2.99 1.377,-2.99 ; 1.171,2.969 1.372,2.969 ; 2.431,2.969 2.581,2.969 2.581,2.939 2.581,-2.99 2.436,-2.99
  lines w0.5: -2.949,-3.452 -2.939,-3.498 -2.911,-3.538 -2.87,-3.564 -2.824,-3.574 -2.776,-3.564 -2.736,-3.538 -2.71,-3.498 -2.7,-3.449 -2.71,-3.401 -2.736,-3.36 -2.776,-3.335 -2.824,-3.325 -2.87,-3.335 -2.911,-3.36 -2.939,-3.401 -2.949,-3.449
Top Paste:
  region: -2.253,3.5 -1.547,3.5 -1.547,2.449 -0.975,2.449 -0.975,3.503 -0.279,3.503 -0.279,2.451 0.29,2.451 0.29,3.508 1.001,3.508 1.001,2.438 1.549,2.438 1.549,3.498 2.25,3.498 2.25,2.441 2.301,2.441 2.301,-1.359 -2.299,-1.359 -2.299,2.441 -2.25,2.441 -2.25,2.443
  region: 1.557,-2.301 2.256,-2.301 2.256,-3.5 1.557,-3.5
  region: 0.287,-2.301 0.986,-2.301 0.986,-3.5 0.287,-3.5
  region: -0.983,-2.301 -0.284,-2.301 -0.284,-3.5 -0.983,-3.5
  region: -2.253,-2.301 -1.554,-2.301 -1.554,-3.5 -2.253,-3.5
Mechanical 2:
  lines w0.3: -2.06,-3.561 -2.05,-3.51 -2.024,-3.465 -1.984,-3.432 -1.935,-3.414 -1.882,-3.414 -1.834,-3.432 -1.793,-3.465 -1.768,-3.51 -1.758,-3.561 -1.768,-3.612 -1.793,-3.658 -1.834,-3.691 -1.882,-3.708 -1.935,-3.708 -1.984,-3.691 -2.024,-3.658 -2.05,-3.612 -2.06,-3.561
Mechanical 6:
  lines w0.051: -2.499,-2.901 -2.499,2.898 2.502,2.898 2.502,-2.901 -2.499,-2.901
Mechanical 8:
  region: -2.438,-3.002 -2.449,-3.033 -2.474,-3.056 -2.507,-3.061 -2.537,-3.045 -2.555,-3.018 -2.555,-2.984 -2.537,-2.957 -2.507,-2.941 -2.474,-2.946 -2.449,-2.969
Mechanical 9:
  region: 1.697,-2.456 2.116,-2.456 2.116,-3.002 1.697,-3.002
  region: 0.427,-2.456 0.846,-2.456 0.846,-3.002 0.427,-3.002
  region: -0.843,-2.456 -0.424,-2.456 -0.424,-3.002 -0.843,-3.002
  region: -2.113,-2.456 -1.694,-2.456 -1.694,-3.002 -2.113,-3.002
  region: -2.108,3 -1.689,3 -1.689,2.349 -2.108,2.349
  region: -0.838,3 -0.419,3 -0.419,2.349 -0.838,2.349
  region: 0.432,3 0.851,3 0.851,2.349 0.432,2.349
  region: 1.692,3 2.111,3 2.111,2.349 1.692,2.349
  region: -1.9,2.38 1.9,2.38 1.9,-1.201 -1.9,-1.201

## PWRM-TH_BXXXXS-2WR3 [mm]
pads (4):
  rect 1.8x1.8 hole 1: 1(-6.35,0)
  round 1.8 hole 1: 2(-3.81,0) 4(1.27,0) 6(6.35,0)
Top Overlay:
  circle w0.5: c-7.5,-5.4 r0.25
  lines w0.254: -7.581,0.903 -8.56,0.903 -8.56,-6.147 11.09,-6.147 ; -5.119,0.903 -4.645,0.903 ; -2.975,0.903 0.435,0.903 ; 2.105,0.903 5.515,0.903 ; 7.185,0.903 11.1,0.903 ; 11.1,-6.147 11.1,0.904
Mechanical 2:
  circle w0.3: c-6.9,-0.6 r0.15
  circle w0.5: c-7.5,-5.4 r0.25
  region: 10.973,-6.147 10.973,0.904 10.982,0.953 11.01,0.994 11.051,1.022 11.1,1.031 11.148,1.022 11.19,0.994 11.217,0.953 11.227,0.904 11.227,-6.147 11.217,-6.195 11.19,-6.237 11.148,-6.264 11.1,-6.274 11.051,-6.264 11.01,-6.237 10.982,-6.195
  region: -8.433,0.903 -8.433,-6.02 11.09,-6.02 11.139,-6.029 11.18,-6.057 11.207,-6.098 11.217,-6.147 11.207,-6.195 11.18,-6.237 11.139,-6.264 11.09,-6.274 -8.56,-6.274 -8.608,-6.264 -8.65,-6.237 -8.677,-6.195 -8.687,-6.147 -8.687,0.903 -8.677,0.952 -8.65,0.993 -8.608,1.021 -8.56,1.03 -8.511,1.021 -8.47,0.993 -8.442,0.952
Mechanical 6:
  lines w0.051: -8.53,-6.1 -8.53,0.9 11.07,0.9 11.07,-6.1 -8.53,-6.1
Mechanical 8:
  region: -8.47,-6.1 -8.47,-6.125 -8.505,-6.16 -8.555,-6.16 -8.59,-6.125 -8.59,-6.1 -8.59,-6.075 -8.555,-6.04 -8.505,-6.04 -8.47,-6.075 -8.47,-6.1
Mechanical 9:
  region: 6.1,-0.15 6.1,0.15 6.6,0.15 6.6,-0.15
  region: 1.02,-0.15 1.02,0.15 1.52,0.15 1.52,-0.15
  region: -4.06,-0.15 -4.06,0.15 -3.56,0.15 -3.56,-0.15
  region: -6.6,0.15 -6.1,0.15 -6.1,-0.15 -6.6,-0.15
3D body "PWRM-TH_BXXXXS-2WR3.step": height 10.16, standoff -4.1, extent -8.428,-6.192 11.222,0.859

## QFN-28_L4.0-W4.0-P0.40-BL-EP2.7 [mm]
pads (29):
  rect 0.2x0.7 smd paste-100 mask+0.051: 1(-1.2,-2) 2(-0.8,-2) 3(-0.4,-2) 4(-0.001,-2) 5(0.4,-2) 6(0.8,-2) 7(1.2,-2) 15(1.2,2) 16(0.8,2) 17(0.4,2) 18(0,2) 19(-0.4,2) 20(-0.8,2) 21(-1.2,2)
  rect 0.7x0.2 smd paste-100 mask+0.051: 8(2,-1.2) 9(2,-0.8) 10(2,-0.4) 11(1.999,0) 12(2,0.4) 13(2,0.8) 14(2,1.2) 22(-2,1.2) 23(-2,0.8) 24(-2,0.4) 25(-2,0) 26(-2,-0.4) 27(-2,-0.8) 28(-2,-1.2)
  rect 2.7x2.7 smd paste-100 mask+0.051: 29(0,0)
Top Overlay:
  lines w0.102: -2,-1.5 -2,-2 -1.5,-2 ; -2,1.5 -2,2 -1.5,2 ; 1.5,-2 2,-2 2,-1.5 ; 1.5,2 2,2 2,1.5
  lines w0.15: -2.22,-1.6 -2.22,-2.21 -1.64,-2.21
Top Paste:
  region: 1.3,1.65 1.3,2.35 1.1,2.35 1.1,1.65
  region: 0.7,2.35 0.7,1.65 0.9,1.65 0.9,2.35
  region: -1.1,1.65 -1.1,2.35 -1.3,2.35 -1.3,1.65
  region: -0.7,1.65 -0.7,2.35 -0.9,2.35 -0.9,1.65
  region: -0.3,1.65 -0.3,2.35 -0.5,2.35 -0.5,1.65
  region: 0.3,2.35 0.3,1.65 0.5,1.65 0.5,2.35
  region: 0.1,1.65 0.1,2.35 -0.1,2.35 -0.1,1.65
  region: 1.08,-1.08 1.08,1.08 -1.08,1.08 -1.08,-1.08
  region: -2.35,1.3 -2.35,1.1 -1.65,1.1 -1.65,1.3
  region: 2.35,1.1 2.35,1.3 1.65,1.3 1.65,1.1
  region: -2.35,0.9 -2.35,0.7 -1.65,0.7 -1.65,0.9
  region: 2.35,0.7 2.35,0.9 1.65,0.9 1.65,0.7
  region: -2.35,0.5 -2.35,0.3 -1.65,0.3 -1.65,0.5
  region: 2.35,0.3 2.35,0.5 1.65,0.5 1.65,0.3
  region: -2.35,0.1 -2.35,-0.1 -1.65,-0.1 -1.65,0.1
  region: 2.349,-0.1 2.349,0.1 1.649,0.1 1.649,-0.1
  region: -2.35,-0.3 -2.35,-0.5 -1.65,-0.5 -1.65,-0.3
  region: 2.35,-0.5 2.35,-0.3 1.65,-0.3 1.65,-0.5
  region: -2.35,-0.7 -2.35,-0.9 -1.65,-0.9 -1.65,-0.7
  region: 2.35,-0.9 2.35,-0.7 1.65,-0.7 1.65,-0.9
  region: -2.35,-1.1 -2.35,-1.3 -1.65,-1.3 -1.65,-1.1
  region: 1.65,-1.1 1.65,-1.3 2.35,-1.3 2.35,-1.1
  region: -1.1,-2.35 -1.1,-1.65 -1.3,-1.65 -1.3,-2.35
  region: -0.101,-1.65 -0.101,-2.35 0.099,-2.35 0.099,-1.65
  region: -0.7,-2.35 -0.7,-1.65 -0.9,-1.65 -0.9,-2.35
  region: -0.3,-2.35 -0.3,-1.65 -0.5,-1.65 -0.5,-2.35
  region: 1.3,-2.35 1.3,-1.65 1.1,-1.65 1.1,-2.35
  region: 0.3,-1.65 0.3,-2.35 0.5,-2.35 0.5,-1.65
  region: 0.9,-2.35 0.9,-1.65 0.7,-1.65 0.7,-2.35
Mechanical 2:
  circle w0.25: c-1.21,-2.35 r0.125
Mechanical 6:
  lines w0.051: -2,-2 -2,2 2,2 2,-2 -2,-2
Mechanical 8:
  region: -1.94,-2 -1.94,-2.025 -1.975,-2.06 -2.025,-2.06 -2.06,-2.025 -2.06,-2 -2.06,-1.975 -2.025,-1.94 -1.975,-1.94 -1.94,-1.975 -1.94,-2
Mechanical 9:
  region: -2,-1.3 -2,-1.1 -1.65,-1.1 -1.65,-1.3
  region: -2,-0.9 -2,-0.7 -1.65,-0.7 -1.65,-0.9
  region: -2,-0.5 -2,-0.3 -1.65,-0.3 -1.65,-0.5
  region: -2,-0.1 -2,0.1 -1.65,0.1 -1.65,-0.1
  region: -2,0.3 -2,0.5 -1.65,0.5 -1.65,0.3
  region: -2,0.7 -2,0.9 -1.65,0.9 -1.65,0.7
  region: -2,1.1 -2,1.3 -1.65,1.3 -1.65,1.1
  region: -1.3,1.65 -1.3,2 -1.1,2 -1.1,1.65
  region: -0.9,1.65 -0.9,2 -0.7,2 -0.7,1.65
  region: -0.5,1.65 -0.5,2 -0.3,2 -0.3,1.65
  region: -0.1,1.65 -0.1,2 0.1,2 0.1,1.65
  region: 0.3,1.65 0.3,2 0.5,2 0.5,1.65
  region: 0.7,1.65 0.7,2 0.9,2 0.9,1.65
  region: 1.1,1.65 1.1,2 1.3,2 1.3,1.65
  region: 1.65,1.1 1.65,1.3 2,1.3 2,1.1
  region: 1.65,0.7 1.65,0.9 2,0.9 2,0.7
  region: 1.65,0.3 1.65,0.5 2,0.5 2,0.3
  region: 1.65,-0.1 1.65,0.1 2,0.1 2,-0.1
  region: 1.65,-0.5 1.65,-0.3 2,-0.3 2,-0.5
  region: 1.65,-0.9 1.65,-0.7 2,-0.7 2,-0.9
  region: 1.65,-1.3 1.65,-1.1 2,-1.1 2,-1.3
  region: -1.3,-2 -1.3,-1.65 -1.1,-1.65 -1.1,-2
  region: -0.9,-2 -0.9,-1.65 -0.7,-1.65 -0.7,-2
  region: -0.5,-2 -0.5,-1.65 -0.3,-1.65 -0.3,-2
  region: 1.1,-2 1.1,-1.65 1.3,-1.65 1.3,-2
  region: 0.7,-2 0.7,-1.65 0.9,-1.65 0.9,-2
  region: 0.3,-2 0.3,-1.65 0.5,-1.65 0.5,-2
  region: -0.101,-2 -0.101,-1.65 0.099,-1.65 0.099,-2
  region: -1.35,1.37 1.35,1.37 1.35,-1.33 -1.35,-1.33
3D body "QFN-28_L4.0-W4.0-P0.40-BL-EP2.7.step": height 0.73, standoff -0.03, extent -2.01,-2.01 2.01,2.01

## QFN-28_L4.0-W4.0-P0.40-BL-EP2.8 [mm]
pads (29):
  rect 0.2x0.7 smd paste-100 mask+0.051: 1(-1.2,-2) 2(-0.8,-2) 3(-0.4,-2) 4(-0.001,-2) 5(0.4,-2) 6(0.8,-2) 7(1.2,-2) 15(1.2,2) 16(0.8,2) 17(0.4,2) 18(0,2) 19(-0.4,2) 20(-0.8,2) 21(-1.2,2)
  rect 0.7x0.2 smd paste-100 mask+0.051: 8(2,-1.2) 9(2,-0.8) 10(2,-0.4) 11(1.999,0) 12(2,0.4) 13(2,0.8) 14(2,1.2) 22(-2,1.2) 23(-2,0.8) 24(-2,0.4) 25(-2,0) 26(-2,-0.4) 27(-2,-0.8) 28(-2,-1.2)
  rect 2.8x2.8 smd paste-100 mask+0.051: 29(0,0.02)
Top Overlay:
  circle w0.1: c-1.905,-2.286 r0.099
  lines w0.102: -2,-1.5 -2,-2 -1.5,-2 ; -2,1.5 -2,2 -1.5,2 ; 1.5,-2 2,-2 2,-1.5 ; 1.5,2 2,2 2,1.5
Top Paste:
  region: -1.12,1.14 1.12,1.14 1.12,-1.1 -1.12,-1.1
  region: -1.65,1.1 -1.65,1.3 -2.35,1.3 -2.35,1.1
  region: -1.65,0.7 -1.65,0.9 -2.35,0.9 -2.35,0.7
  region: -1.65,0.3 -1.65,0.5 -2.35,0.5 -2.35,0.3
  region: -1.65,-0.1 -1.65,0.1 -2.35,0.1 -2.35,-0.1
  region: -1.65,-0.5 -1.65,-0.3 -2.35,-0.3 -2.35,-0.5
  region: -1.65,-0.9 -1.65,-0.7 -2.35,-0.7 -2.35,-0.9
  region: -1.65,-1.3 -1.65,-1.1 -2.35,-1.1 -2.35,-1.3
  region: 2.35,-1.3 2.35,-1.1 1.65,-1.1 1.65,-1.3
  region: 2.35,-0.9 2.35,-0.7 1.65,-0.7 1.65,-0.9
  region: 2.35,-0.5 2.35,-0.3 1.65,-0.3 1.65,-0.5
  region: 2.35,-0.1 2.35,0.1 1.65,0.1 1.65,-0.1
  region: 2.35,0.3 2.35,0.5 1.65,0.5 1.65,0.3
  region: 2.35,0.7 2.35,0.9 1.65,0.9 1.65,0.7
  region: 2.35,1.1 2.35,1.3 1.65,1.3 1.65,1.1
  region: 1.3,-1.65 1.1,-1.65 1.1,-2.35 1.3,-2.35
  region: 0.9,-1.65 0.7,-1.65 0.7,-2.35 0.9,-2.35
  region: 0.5,-1.65 0.3,-1.65 0.3,-2.35 0.5,-2.35
  region: 0.1,-1.65 -0.1,-1.65 -0.1,-2.35 0.1,-2.35
  region: -0.3,-1.65 -0.5,-1.65 -0.5,-2.35 -0.3,-2.35
  region: -0.7,-1.65 -0.9,-1.65 -0.9,-2.35 -0.7,-2.35
  region: -1.1,-1.65 -1.3,-1.65 -1.3,-2.35 -1.1,-2.35
  region: 1.3,2.35 1.1,2.35 1.1,1.65 1.3,1.65
  region: 0.9,2.35 0.7,2.35 0.7,1.65 0.9,1.65
  region: 0.5,2.35 0.3,2.35 0.3,1.65 0.5,1.65
  region: 0.1,2.35 -0.1,2.35 -0.1,1.65 0.1,1.65
  region: -0.3,2.35 -0.5,2.35 -0.5,1.65 -0.3,1.65
  region: -0.7,2.35 -0.9,2.35 -0.9,1.65 -0.7,1.65
  region: -1.1,2.35 -1.3,2.35 -1.3,1.65 -1.1,1.65
Mechanical 2:
  circle w0.254: c-1.24,-2.25 r0.127
Mechanical 3:
  lines w0.051: -2,-2 -2,2 2,2 2,-2 -2,-2
Mechanical 5:
  region: -1.94,-2 -1.94,-2.025 -1.975,-2.06 -2.025,-2.06 -2.06,-2.025 -2.06,-2 -2.06,-1.975 -2.025,-1.94 -1.975,-1.94 -1.94,-1.975 -1.94,-2
Mechanical 6:
  region: -1.65,-1.1 -1.65,-1.3 -2,-1.3 -2,-1.1
  region: -1.65,-0.7 -1.65,-0.9 -2,-0.9 -2,-0.7
  region: -1.65,-0.3 -1.65,-0.5 -2,-0.5 -2,-0.3
  region: -1.65,0.1 -1.65,-0.1 -2,-0.1 -2,0.1
  region: -1.65,0.5 -1.65,0.3 -2,0.3 -2,0.5
  region: -1.65,0.9 -1.65,0.7 -2,0.7 -2,0.9
  region: -1.65,1.3 -1.65,1.1 -2,1.1 -2,1.3
  region: -1.3,2 -1.1,2 -1.1,1.65 -1.3,1.65
  region: -0.9,2 -0.7,2 -0.7,1.65 -0.9,1.65
  region: -0.5,2 -0.3,2 -0.3,1.65 -0.5,1.65
  region: -0.1,2 0.1,2 0.1,1.65 -0.1,1.65
  region: 0.3,2 0.5,2 0.5,1.65 0.3,1.65
  region: 0.7,2 0.9,2 0.9,1.65 0.7,1.65
  region: 1.1,2 1.3,2 1.3,1.65 1.1,1.65
  region: 1.65,1.1 1.65,1.3 2,1.3 2,1.1
  region: 1.65,0.7 1.65,0.9 2,0.9 2,0.7
  region: 1.65,0.3 1.65,0.5 2,0.5 2,0.3
  region: 1.65,-0.1 1.65,0.1 2,0.1 2,-0.1
  region: 1.65,-0.5 1.65,-0.3 2,-0.3 2,-0.5
  region: 1.65,-0.9 1.65,-0.7 2,-0.7 2,-0.9
  region: 1.65,-1.3 1.65,-1.1 2,-1.1 2,-1.3
  region: -1.1,-2 -1.3,-2 -1.3,-1.65 -1.1,-1.65
  region: -0.7,-2 -0.9,-2 -0.9,-1.65 -0.7,-1.65
  region: -0.3,-2 -0.5,-2 -0.5,-1.65 -0.3,-1.65
  region: 1.3,-2 1.1,-2 1.1,-1.65 1.3,-1.65
  region: 0.9,-2 0.7,-2 0.7,-1.65 0.9,-1.65
  region: 0.5,-2 0.3,-2 0.3,-1.65 0.5,-1.65
  region: 0.099,-2 -0.101,-2 -0.101,-1.65 0.099,-1.65
  region: -1.4,1.42 1.4,1.42 1.4,-1.38 -1.4,-1.38

## QFN-40_L5.0-W5.0-P0.40-BL-EP3.7 [mm]
pads (41):
  rect 0.2x0.8 smd paste-100 mask+0.05: 1(-1.8,-2.499) 2(-1.4,-2.499) 3(-1,-2.499) 4(-0.6,-2.499) 5(-0.2,-2.499) 6(0.2,-2.499) 7(0.6,-2.499) 8(1,-2.499) 9(1.4,-2.499) 10(1.8,-2.499) 21(1.8,2.499) 22(1.4,2.499) 23(1,2.499) 24(0.6,2.499) 25(0.2,2.499) 26(-0.2,2.499) 27(-0.6,2.499) 28(-1,2.499) 29(-1.4,2.499) 30(-1.8,2.499)
  rect 0.8x0.2 smd paste-100 mask+0.05: 11(2.499,-1.8) 12(2.499,-1.4) 13(2.499,-1) 14(2.499,-0.6) 15(2.499,-0.2) 16(2.499,0.2) 17(2.499,0.6) 18(2.499,1) 19(2.499,1.4) 20(2.499,1.8) 31(-2.499,1.8) 32(-2.499,1.4) 33(-2.499,1) 34(-2.499,0.6) 35(-2.499,0.2) 36(-2.499,-0.2) 37(-2.499,-0.6) 38(-2.499,-1) 39(-2.499,-1.4) 40(-2.499,-1.8)
  rect 3.7x3.7 smd paste-100 mask+0.05: 41(0,0)
Top Overlay:
  lines w0.2: -2.7,-2.2 -2.7,-2.7 -2.2,-2.7 ; -2.7,2.2 -2.7,2.7 -2.2,2.7 ; 2.2,-2.7 2.7,-2.7 2.7,-2.2 ; 2.2,2.7 2.7,2.7 2.7,2.2
  lines w0.3: -2.499,-3.051 ccw(c-2.498,-3.201) -2.497,-3.051
Top Paste:
  drawing of 41 lines, arcs and shapes, not listed
Mechanical 2:
  circle w0.3: c-1.82,-3.12 r0.15
Mechanical 6:
  lines w0.051: -2.5,-2.5 2.5,-2.5 2.5,2.5 -2.5,2.5 -2.5,-2.5
Mechanical 8:
  region: -2.38,-2.5 -2.38,-2.55 -2.45,-2.62 -2.55,-2.62 -2.62,-2.55 -2.62,-2.5 -2.62,-2.45 -2.55,-2.38 -2.45,-2.38 -2.38,-2.45 -2.38,-2.5
Mechanical 9:
  drawing of 41 lines, arcs and shapes, not listed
